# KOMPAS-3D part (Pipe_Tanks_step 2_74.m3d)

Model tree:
1. X Axis
2. Y Axis
3. Z Axis  (labels: Bend 90 Dn 50; Pipe Dn 50; T-Bend Dn 50)
     Òîëùèíà ñòåíêè 1 = 1

Referenced files in C:\Documents and Settings\kashirsky\Мои документы\Camtasia Studio\Pipelines3D\Tanks\: Tanks_step 2.a3d
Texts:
  Pipe Dn 50
  Steel ASTM A295
  Three Point Plane
  Plane at Angle
  Line and Point Plane
  Axis through Two Vertices
  Axis of Feature
  Axis of Conical Surface
  Axis through Edge
  Trim by Surface
  Trim by Sketch
  Feature with No History
  Intersection Axis of Two Planes
  Two Line Plane
  Line and Face Plane
  Bend by line
  Hole in sheet body
  Cut in sheet body
  Point in CM
  Linear Dimension from Line to Point
  Surface Finish Symbol
  Geometric Tolerance Symbol
  Leader #1
  Leader #2
  Leader #3
  Shape Deviations and Datum
  Node point number
  Mark of coordination axis
  Node point designation
  Mark/Reference designation with leader
  Mark/reference designation on line
  Mark/Reference designation without leader
  Bend 90 Dn 50
  T-Bend Dn 50
  Plane of section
